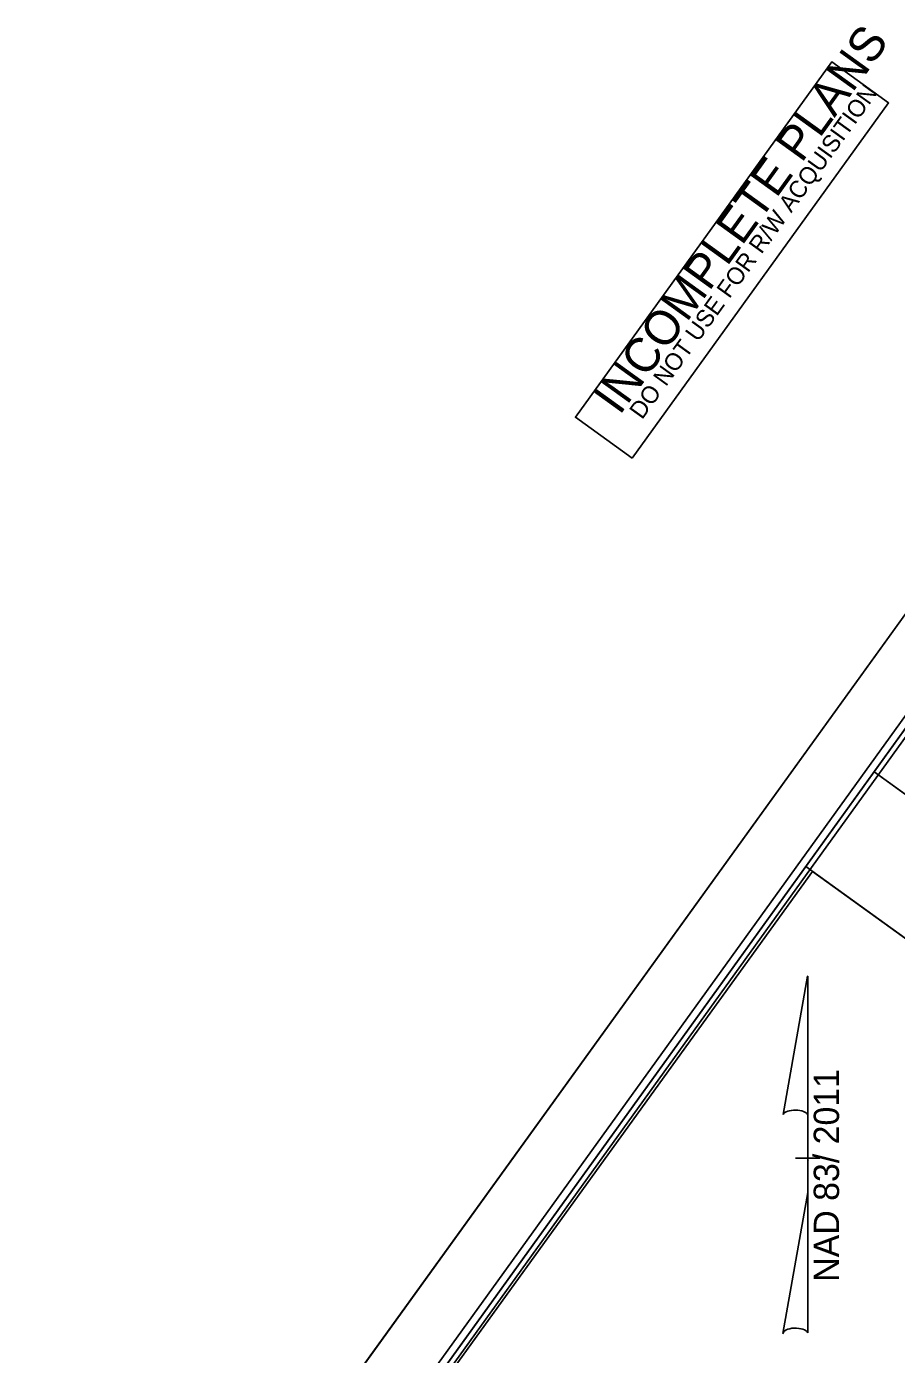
# Model space of a CAD drawing. Extents: x 2186840 to 2191350, y 386817 to 390793.
# Drawn here: x 2190068.9 to 2190360.8, y 388438.1 to 388883.7 of the extents above; entities that cross this region are included whole.
import ezdxf

# ---------------------------------------------------------------- set-up
doc = ezdxf.new("R2010")
doc.units = 0
for name, color, linetype in [('Prop North Arrow NAD83 for Plan Sheets CELL', 7, 'Continuous'), ('Sheet Clip Boundary CELL', 7, 'Continuous'), ('Sheet Cutting Line CELL', 7, 'Continuous'), ('Sheet Layout Plan Border', 7, 'Continuous'), ('Sheet North Arrow Point CELL', 7, 'Continuous'), ('Sheet Plan CELL', 7, 'Continuous'), ('Sheet Plan Layout CELL', 7, 'Continuous'), ('Sheet Plot Border Inside CELL', 7, 'Continuous'), ('Sheet Plot Border Outside CELL', 7, 'Continuous'), ('Sheet Sticker Incomplete CELL', 7, 'Continuous')]:
    doc.layers.add(name, color=color, linetype=linetype)

msp = doc.modelspace()

# ---------------------------------------------------------------- linework, layer by layer
at = {"layer": 'Prop North Arrow NAD83 for Plan Sheets CELL'}
for p, q in [((2190322.78, 388518.66), (2190330.98, 388565.01)), ((2190331.03, 388565.01), (2190330.98, 388565.01)), ((2190331.03, 388565.01), (2190330.98, 388565.01)), ((2190331.03, 388565.01), (2190331.03, 388517.21)), ((2190331.03, 388492.41), (2190331.03, 388518.61)), ((2190331.03, 388517.21), (2190331.03, 388518.56)), ((2190327.03, 388504.01), (2190326.98, 388504.01)), ((2190330.58, 388504.01), (2190327.03, 388504.01)), ((2190327.08, 388504.01), (2190335.08, 388504.01)), ((2190331.03, 388492.41), (2190322.68, 388445.16)), ((2190331.08, 388445.36), (2190331.03, 388492.41))]:
    msp.add_line(p, q, dxfattribs=at)
for centre, start_param, end_param in [((2190326.91, 388518.17), 0.216388, 2.908219), ((2190326.91, 388445), 0.201328, 3.141593)]:
    msp.add_ellipse(centre, major_axis=(4.23, -0.03), ratio=0.461098, start_param=start_param, end_param=end_param, dxfattribs=at)
at = {"layer": 'Sheet Clip Boundary CELL'}
msp.add_lwpolyline([(2189820.17, 387477.49), (2190138.13, 387247.68), (2190214.83, 387198.27), (2190505.63, 387605.8), (2190773.91, 387420.42), (2191313.5, 388179.15), (2190637.62, 388666.29), (2190501.89, 388478.1), (2190332.62, 388600.18), (2189623.63, 387618.74)], close=True, dxfattribs=at)
at = {"layer": 'Sheet Cutting Line CELL'}
msp.add_line((2190462.01, 388822.81), (2189477.28, 387457.36), dxfattribs=at)
at = {"layer": 'Sheet Layout Plan Border'}
msp.add_lwpolyline([(2190469.75, 387008.54), (2191313.6, 388178.64), (2190637.85, 388665.97), (2190536.83, 388525.9), (2190366.46, 388648.77), (2189623.63, 387618.74)], close=True, dxfattribs=at)
at = {"layer": 'Sheet North Arrow Point CELL'}
msp.add_line((2190331.37, 388503.21), (2190331.37, 388503.21), dxfattribs=at)
at = {"layer": 'Sheet Plan CELL'}
for points in [[(2190470.32, 388795.89), (2189592.9, 387579.24), (2190444.54, 386965.06), (2191321.95, 388181.69)], [(2190353.28, 388633.62), (2190470.32, 388795.89), (2190490.62, 388781.21), (2190373.63, 388618.95)], [(2190444.54, 386965.06), (2189592.91, 387579.2), (2190353.28, 388633.62), (2190475, 388545.85), (2190592.02, 388708.09), (2191321.95, 388181.69)]]:
    msp.add_lwpolyline(points, close=True, dxfattribs=at)
at = {"layer": 'Sheet Plan Layout CELL'}
for points in [[(2190501.89, 388478.1), (2190641.85, 388672.18), (2190470.33, 388795.9), (2190330.36, 388601.81)], [(2189592.91, 387579.2), (2190444.54, 386965.06), (2191321.94, 388181.68), (2190641.84, 388672.15), (2190501.89, 388478.1), (2190330.36, 388601.81)]]:
    msp.add_lwpolyline(points, close=True, dxfattribs=at)
at = {"layer": 'Sheet Plot Border Inside CELL'}
msp.add_lwpolyline([(2190356.8, 386839.1), (2191331.28, 388190.36), (2190475.6, 388807.46), (2189501.11, 387456.2)], close=True, dxfattribs=at)
at = {"layer": 'Sheet Plot Border Outside CELL'}
msp.add_lwpolyline([(2190365.42, 386816.86), (2191350.15, 388182.31), (2190462.01, 388822.81), (2189477.28, 387457.36)], close=True, dxfattribs=at)
at = {"layer": 'Sheet Sticker Incomplete CELL'}
msp.add_lwpolyline([(2190272.17, 388738.87), (2190253.11, 388752.62), (2190339.09, 388871.85), (2190358.15, 388858.1)], close=True, dxfattribs=at)

# ---------------------------------------------------------------- texts
at = {"layer": 'Prop North Arrow NAD83 for Plan Sheets CELL'}
msp.add_text('NAD 83/ 2011', height=8.5, rotation=90, dxfattribs=at).set_placement((2190341.55, 388462.49))
at = {"layer": 'Sheet Sticker Incomplete CELL'}
for s, height, p in [('INCOMPLETE PLANS', 11.52, (2190267.91, 388752.97)), ('DO NOT USE FOR R/W ACQUISITION', 5.76, (2190275.45, 388751.55))]:
    msp.add_text(s, height=height, rotation=54.2018, dxfattribs=at).set_placement(p)

doc.saveas('drawing.dxf')
